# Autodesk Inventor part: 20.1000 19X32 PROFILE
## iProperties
Company: MiniTec Framing Systems, LLC
Created: 2007-05
Part Number: 20.1000 19X32 PROFILE
Material: Aluminum-6061
Document SubType Name: Modeling
Designer: Andy Moles
Density: 2.71 g/cm^3
Author: Andy Moles
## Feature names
1. Extrusion1
2. Hole1
